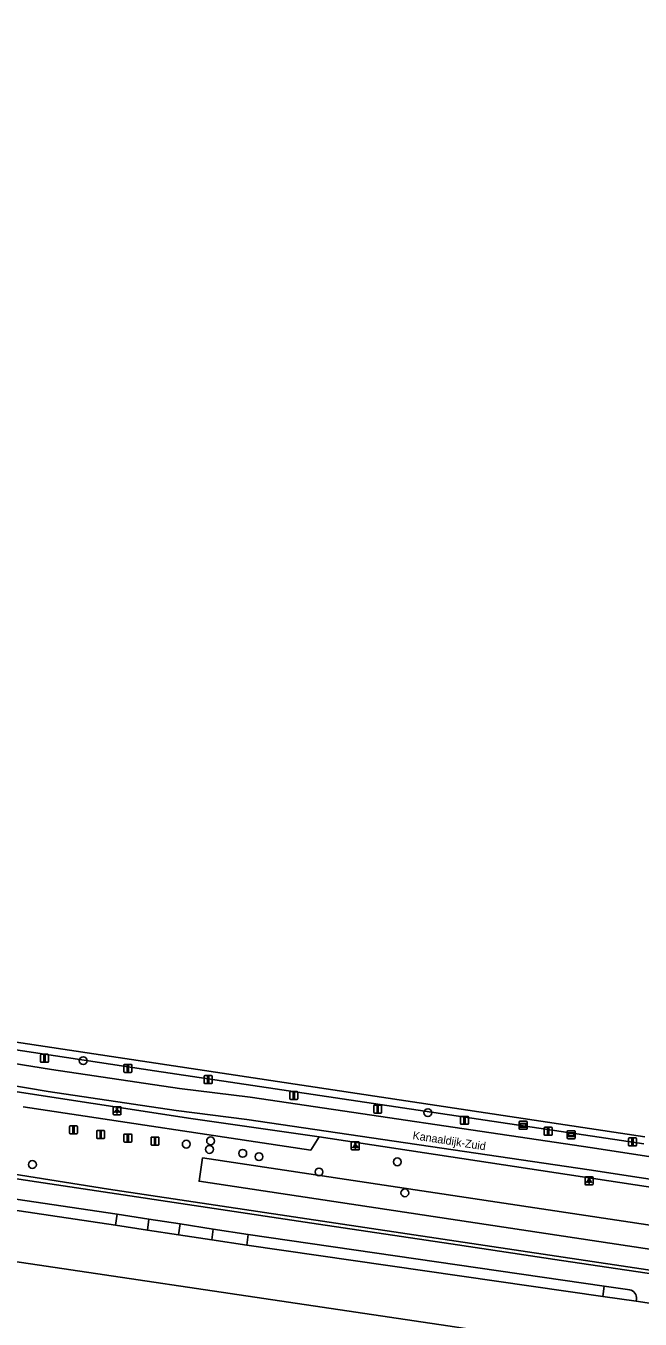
# Model space of a CAD drawing. Extents: x 163046 to 165074, y 382019 to 382874.
# Drawn here: x 164207.3 to 164284.1, y 382656.8 to 382818.4 of the extents above; entities that cross this region are included whole.
import ezdxf

# ---------------------------------------------------------------- set-up
doc = ezdxf.new("R2010")
doc.units = 0
for name, color, linetype in [('IMGEO_Afsluitpaal', 7, 'Continuous'), ('IMGEO_Boom', 7, 'Continuous'), ('IMGEO_Fietspad_gesloten', 7, 'Continuous'), ('IMGEO_Fietspad_open', 7, 'Continuous'), ('IMGEO_Groenvoorziening', 7, 'Continuous'), ('IMGEO_Hek', 7, 'Continuous'), ('IMGEO_Lichtpunt', 7, 'Continuous'), ('IMGEO_Openbare_ruimte_label', 7, 'Continuous'), ('IMGEO_Rijbaan_lokaal_gesloten', 7, 'Continuous'), ('IMGEO_Rijbaan_lokaal_halfverhard', 7, 'Continuous'), ('IMGEO_Verklikker', 7, 'Continuous'), ('IMGEO_Voetpad_open', 7, 'Continuous'), ('IMGEO_Waterloop', 7, 'Continuous')]:
    doc.layers.add(name, color=color, linetype=linetype)

msp = doc.modelspace()

# ---------------------------------------------------------------- linework, layer by layer
at = {"layer": 'IMGEO_Afsluitpaal'}
for p, q in [((164209.15, 382689.01), (164209.15, 382689.81)), ((164209.15, 382689.81), (164209.15, 382689.01)), ((164209.25, 382689.91), (164210.04, 382689.91)), ((164210.04, 382689.91), (164209.25, 382689.91)), ((164210.04, 382688.91), (164209.25, 382688.91)), ((164209.25, 382688.91), (164210.04, 382688.91)), ((164210.14, 382689.81), (164210.14, 382689.01)), ((164210.14, 382689.01), (164210.14, 382689.81)), ((164219.56, 382687.75), (164219.56, 382688.55)), ((164219.56, 382688.55), (164219.56, 382687.75)), ((164219.66, 382688.65), (164220.45, 382688.65)), ((164220.45, 382688.65), (164219.66, 382688.65)), ((164220.55, 382688.55), (164220.55, 382687.75)), ((164220.55, 382687.75), (164220.55, 382688.55)), ((164220.45, 382687.65), (164219.66, 382687.65)), ((164219.66, 382687.65), (164220.45, 382687.65)), ((164229.6, 382686.35), (164229.6, 382687.15)), ((164229.6, 382687.15), (164229.6, 382686.35)), ((164229.7, 382687.25), (164230.49, 382687.25)), ((164230.49, 382687.25), (164229.7, 382687.25)), ((164230.59, 382687.15), (164230.59, 382686.35)), ((164230.59, 382686.35), (164230.59, 382687.15)), ((164230.49, 382686.25), (164229.7, 382686.25)), ((164229.7, 382686.25), (164230.49, 382686.25)), ((164240.31, 382684.36), (164240.31, 382685.16)), ((164240.31, 382685.16), (164240.31, 382684.36)), ((164240.41, 382685.26), (164241.2, 382685.26)), ((164241.2, 382685.26), (164240.41, 382685.26)), ((164241.3, 382685.16), (164241.3, 382684.36)), ((164241.3, 382684.36), (164241.3, 382685.16)), ((164241.2, 382684.26), (164240.41, 382684.26)), ((164240.41, 382684.26), (164241.2, 382684.26)), ((164250.9, 382683.56), (164251.68, 382683.56)), ((164251.68, 382683.56), (164250.9, 382683.56)), ((164250.8, 382682.66), (164250.8, 382683.46)), ((164250.8, 382683.46), (164250.8, 382682.66)), ((164251.68, 382682.56), (164250.9, 382682.56)), ((164250.9, 382682.56), (164251.68, 382682.56)), ((164251.78, 382683.46), (164251.78, 382682.66)), ((164251.78, 382682.66), (164251.78, 382683.46)), ((164261.65, 382681.26), (164261.65, 382682.05)), ((164261.65, 382682.05), (164261.65, 382681.26)), ((164261.75, 382682.15), (164262.54, 382682.15)), ((164262.54, 382682.15), (164261.75, 382682.15)), ((164262.64, 382682.05), (164262.64, 382681.26)), ((164262.64, 382681.26), (164262.64, 382682.05)), ((164212.77, 382680.07), (164212.77, 382680.87)), ((164212.77, 382680.87), (164212.77, 382680.07)), ((164212.87, 382680.97), (164213.66, 382680.97)), ((164213.66, 382680.97), (164212.87, 382680.97)), ((164213.76, 382680.87), (164213.76, 382680.07)), ((164213.76, 382680.07), (164213.76, 382680.87)), ((164216.26, 382680.38), (164217.05, 382680.38)), ((164217.05, 382680.38), (164216.26, 382680.38)), ((164262.54, 382681.16), (164261.75, 382681.16)), ((164261.75, 382681.16), (164262.54, 382681.16)), ((164272.1, 382679.89), (164272.1, 382680.69)), ((164272.1, 382680.69), (164272.1, 382679.89)), ((164272.2, 382680.79), (164272.99, 382680.79)), ((164272.99, 382680.79), (164272.2, 382680.79)), ((164273.09, 382680.69), (164273.09, 382679.89)), ((164273.09, 382679.89), (164273.09, 382680.69)), ((164213.66, 382679.97), (164212.87, 382679.97)), ((164212.87, 382679.97), (164213.66, 382679.97)), ((164216.16, 382679.48), (164216.16, 382680.28)), ((164216.16, 382680.28), (164216.16, 382679.48)), ((164217.05, 382679.38), (164216.26, 382679.38)), ((164216.26, 382679.38), (164217.05, 382679.38)), ((164217.15, 382680.28), (164217.15, 382679.48)), ((164217.15, 382679.48), (164217.15, 382680.28)), ((164219.56, 382679.04), (164219.56, 382679.84)), ((164219.56, 382679.84), (164219.56, 382679.04)), ((164219.66, 382679.94), (164220.45, 382679.94)), ((164220.45, 382679.94), (164219.66, 382679.94)), ((164220.45, 382678.94), (164219.66, 382678.94)), ((164219.66, 382678.94), (164220.45, 382678.94)), ((164220.55, 382679.84), (164220.55, 382679.04)), ((164220.55, 382679.04), (164220.55, 382679.84)), ((164222.96, 382678.67), (164222.96, 382679.47)), ((164222.96, 382679.47), (164222.96, 382678.67)), ((164223.06, 382679.57), (164223.85, 382679.57)), ((164223.85, 382679.57), (164223.06, 382679.57)), ((164223.95, 382679.47), (164223.95, 382678.67)), ((164223.95, 382678.67), (164223.95, 382679.47)), ((164272.99, 382679.79), (164272.2, 382679.79)), ((164272.2, 382679.79), (164272.99, 382679.79)), ((164282.66, 382678.56), (164282.66, 382679.36)), ((164282.66, 382679.36), (164282.66, 382678.56)), ((164282.76, 382679.46), (164283.55, 382679.46)), ((164283.55, 382679.46), (164282.76, 382679.46)), ((164283.65, 382679.36), (164283.65, 382678.56)), ((164283.65, 382678.56), (164283.65, 382679.36)), ((164223.85, 382678.57), (164223.06, 382678.57)), ((164223.06, 382678.57), (164223.85, 382678.57)), ((164283.55, 382678.46), (164282.76, 382678.46)), ((164282.76, 382678.46), (164283.55, 382678.46))]:
    msp.add_line(p, q, dxfattribs=at)
for points in [[(164209.57, 382689.78), (164209.72, 382689.78), (164209.72, 382689.03), (164209.57, 382689.03), (164209.57, 382689.78)], [(164219.98, 382688.53), (164220.13, 382688.53), (164220.13, 382687.78), (164219.98, 382687.78), (164219.98, 382688.53)], [(164230.02, 382687.12), (164230.17, 382687.12), (164230.17, 382686.38), (164230.02, 382686.38), (164230.02, 382687.12)], [(164240.73, 382685.13), (164240.88, 382685.13), (164240.88, 382684.38), (164240.73, 382684.38), (164240.73, 382685.13)], [(164251.21, 382683.43), (164251.37, 382683.43), (164251.37, 382682.68), (164251.21, 382682.68), (164251.21, 382683.43)], [(164262.07, 382682.03), (164262.22, 382682.03), (164262.22, 382681.28), (164262.07, 382681.28), (164262.07, 382682.03)], [(164213.19, 382680.85), (164213.34, 382680.85), (164213.34, 382680.1), (164213.19, 382680.1), (164213.19, 382680.85)], [(164272.52, 382680.66), (164272.67, 382680.66), (164272.67, 382679.91), (164272.52, 382679.91), (164272.52, 382680.66)], [(164216.58, 382680.26), (164216.73, 382680.26), (164216.73, 382679.51), (164216.58, 382679.51), (164216.58, 382680.26)], [(164219.98, 382679.82), (164220.13, 382679.82), (164220.13, 382679.07), (164219.98, 382679.07), (164219.98, 382679.82)], [(164223.38, 382679.45), (164223.53, 382679.45), (164223.53, 382678.7), (164223.38, 382678.7), (164223.38, 382679.45)], [(164283.08, 382679.34), (164283.23, 382679.34), (164283.23, 382678.59), (164283.08, 382678.59), (164283.08, 382679.34)]]:
    msp.add_lwpolyline(points, dxfattribs=at)
for centre, start, end in [((164209.25, 382689.81), 90, 180), ((164209.25, 382689.81), 90, 180), ((164209.25, 382689.01), 180, 270), ((164209.25, 382689.01), 180, 270), ((164210.04, 382689.81), 0, 90), ((164210.04, 382689.81), 360, 90), ((164210.04, 382689.01), 270, 0), ((164210.04, 382689.01), 270, 0), ((164219.66, 382688.55), 90, 180), ((164219.66, 382688.55), 90, 180), ((164220.45, 382688.55), 0, 90), ((164220.45, 382688.55), 360, 90), ((164219.66, 382687.75), 180, 270), ((164219.66, 382687.75), 180, 270), ((164220.45, 382687.75), 270, 0), ((164220.45, 382687.75), 270, 0), ((164229.7, 382687.15), 90, 180), ((164229.7, 382687.15), 90, 180), ((164230.49, 382687.15), 0, 90), ((164230.49, 382687.15), 360, 90), ((164229.7, 382686.35), 180, 270), ((164229.7, 382686.35), 180, 270), ((164230.49, 382686.35), 270, 0), ((164230.49, 382686.35), 270, 0), ((164240.41, 382685.16), 90, 180), ((164240.41, 382685.16), 90, 180), ((164241.2, 382685.16), 0, 90), ((164241.2, 382685.16), 360, 90), ((164240.41, 382684.36), 180, 270), ((164240.41, 382684.36), 180, 270), ((164241.2, 382684.36), 270, 0), ((164241.2, 382684.36), 270, 0), ((164250.9, 382683.46), 90, 180), ((164250.9, 382683.46), 90, 180), ((164251.68, 382683.46), 0, 90), ((164251.68, 382683.46), 360, 90), ((164250.9, 382682.66), 180, 270), ((164250.9, 382682.66), 180, 270), ((164251.68, 382682.66), 270, 0), ((164251.68, 382682.66), 270, 0), ((164261.75, 382682.05), 90, 180), ((164261.75, 382682.05), 90, 180), ((164262.54, 382682.05), 0, 90), ((164262.54, 382682.05), 360, 90), ((164212.87, 382680.87), 90, 180), ((164212.87, 382680.87), 90, 180), ((164213.66, 382680.87), 0, 90), ((164213.66, 382680.87), 360, 90), ((164216.26, 382680.28), 90, 180), ((164216.26, 382680.28), 90, 180), ((164217.05, 382680.28), 0, 90), ((164217.05, 382680.28), 360, 90), ((164261.75, 382681.26), 180, 270), ((164261.75, 382681.26), 180, 270), ((164262.54, 382681.26), 270, 0), ((164262.54, 382681.26), 270, 0), ((164272.2, 382680.69), 90, 180), ((164272.2, 382680.69), 90, 180), ((164272.99, 382680.69), 0, 90), ((164272.99, 382680.69), 360, 90), ((164212.87, 382680.07), 180, 270), ((164212.87, 382680.07), 180, 270), ((164213.66, 382680.07), 270, 0), ((164213.66, 382680.07), 270, 0), ((164216.26, 382679.48), 180, 270), ((164216.26, 382679.48), 180, 270), ((164217.05, 382679.48), 270, 0), ((164217.05, 382679.48), 270, 0), ((164219.66, 382679.84), 90, 180), ((164219.66, 382679.84), 90, 180), ((164219.66, 382679.04), 180, 270), ((164219.66, 382679.04), 180, 270), ((164220.45, 382679.84), 0, 90), ((164220.45, 382679.84), 360, 90), ((164220.45, 382679.04), 270, 0), ((164220.45, 382679.04), 270, 0), ((164223.06, 382679.47), 90, 180), ((164223.06, 382679.47), 90, 180), ((164223.06, 382678.67), 180, 270), ((164223.06, 382678.67), 180, 270), ((164223.85, 382679.47), 0, 90), ((164223.85, 382679.47), 360, 90), ((164223.85, 382678.67), 270, 0), ((164223.85, 382678.67), 270, 0), ((164272.2, 382679.89), 180, 270), ((164272.2, 382679.89), 180, 270), ((164272.99, 382679.89), 270, 0), ((164272.99, 382679.89), 270, 0), ((164282.76, 382679.36), 90, 180), ((164282.76, 382679.36), 90, 180), ((164283.55, 382679.36), 0, 90), ((164283.55, 382679.36), 360, 90), ((164282.76, 382678.56), 180, 270), ((164282.76, 382678.56), 180, 270), ((164283.55, 382678.56), 270, 0), ((164283.55, 382678.56), 270, 0)]:
    msp.add_arc(centre, 0.1, start, end, dxfattribs=at)
at = {"layer": 'IMGEO_Boom'}
for centre in [(164214.48, 382689.11), (164257.56, 382682.62), (164227.36, 382678.68), (164230.4, 382679.09), (164230.26, 382678.02), (164234.42, 382677.53), (164236.45, 382677.11), (164208.13, 382676.13), (164243.95, 382675.2), (164253.74, 382676.47), (164254.69, 382672.59)]:
    msp.add_circle(centre, 0.489, dxfattribs=at)
at = {"layer": 'IMGEO_Fietspad_gesloten'}
for points in [[(164290.62, 382661.73), (164274.25, 382664.12), (164260.42, 382666.24), (164243.89, 382668.69), (164144.23, 382683.65), (164123, 382686.71), (164101.01, 382689.99), (164076.37, 382693.78), (164055.27, 382696.95), (164027.35, 382701.08), (164001.81, 382704.9), (163972.99, 382709.21), (163941.3, 382713.95), (163899.36, 382720.17), (163864.59, 382725.29), (163853.75, 382726.93), (163828.34, 382730.66), (163782.57, 382737.3), (163742.98, 382743.16), (163672.74, 382753.5), (163608.81, 382762.9), (163587.4, 382766.11), (163537.53, 382773.31), (163534.17, 382773.83)], [(163935.71, 382729.35), (163983.8, 382722.23), (164052.71, 382712.03), (164052.69, 382711.93), (164086.54, 382706.99), (164187.43, 382691.72), (164210.53, 382688.01), (164226.5, 382685.65), (164235.35, 382684.54), (164278.14, 382678.22), (164284.35, 382677.28), (164396.3, 382660.19), (164454.95, 382651.33), (164514.06, 382642.55), (164543.13, 382638.08), (164564.45, 382634.88), (164577.4, 382632.94), (164578.83, 382632.68), (164590.1, 382630.98)], [(164085.34, 382689.67), (164218.72, 382669.95)], [(164218.72, 382669.95), (164222.69, 382669.32)], [(164222.69, 382669.32), (164226.59, 382668.71)], [(164226.59, 382668.71), (164230.72, 382668.06)], [(164230.72, 382668.06), (164235.1, 382667.37)], [(164235.1, 382667.37), (164279.62, 382660.93)], [(164279.62, 382660.93), (164282.79, 382660.47)], [(164283.63, 382659.34), (164283.59, 382659.04)]]:
    msp.add_lwpolyline(points, dxfattribs=at)
msp.add_arc((164282.64, 382659.48), 0.999, 351.5194, 81.6371, dxfattribs=at)
at = {"layer": 'IMGEO_Fietspad_open'}
for points in [[(164226.4, 382667.35), (164226.59, 382668.71)], [(164230.72, 382668.06), (164230.55, 382666.71)]]:
    msp.add_lwpolyline(points, dxfattribs=at)
at = {"layer": 'IMGEO_Groenvoorziening'}
for points in [[(163359.37, 382797.83), (163374.85, 382798.03), (163401.89, 382794.15), (163410.94, 382792.85), (163500, 382779.47), (163535.41, 382774.6), (163550.62, 382772.33), (163693.06, 382751.36), (163828.8, 382731.36), (163846.1, 382728.88), (163873.33, 382724.84), (163916.5, 382718.52), (163943.51, 382714.37), (163981.6, 382708.67), (164080.42, 382694.02), (164103.91, 382690.52), (164197.42, 382676.27), (164217.65, 382673.07), (164282.56, 382663.33), (164518.36, 382627.93)], [(164284.55, 382678.7), (164223.39, 382687.83), (164004.16, 382721.06), (164000, 382721.52), (163996.62, 382722), (163984.14, 382724.05), (163984.26, 382724.67)], [(164243.96, 382679.59), (164242.92, 382677.94), (164206.98, 382683.34)]]:
    msp.add_lwpolyline(points, dxfattribs=at)
at = {"layer": 'IMGEO_Hek'}
for points in [[(164282.56, 382663.33), (164217.65, 382673.07), (164197.42, 382676.27), (164103.91, 382690.52), (164080.42, 382694.02), (163981.6, 382708.67)], [(164518.36, 382627.93), (164282.56, 382663.33)]]:
    msp.add_lwpolyline(points, dxfattribs=at)
at = {"layer": 'IMGEO_Lichtpunt'}
for p, q in [((164218.21, 382683.26), (164218.21, 382682.46)), ((164218.21, 382683.26), (164218.21, 382682.46)), ((164219.11, 382683.36), (164218.3, 382683.36)), ((164219.11, 382683.36), (164218.3, 382683.36)), ((164218.3, 382682.36), (164219.11, 382682.36)), ((164218.3, 382682.36), (164219.11, 382682.36)), ((164219.2, 382682.46), (164219.2, 382683.26)), ((164219.2, 382682.46), (164219.2, 382683.26)), ((164247.99, 382678.86), (164247.99, 382678.05)), ((164247.99, 382678.86), (164247.99, 382678.05)), ((164248.89, 382678.95), (164248.09, 382678.95)), ((164248.89, 382678.95), (164248.09, 382678.95)), ((164248.99, 382678.05), (164248.99, 382678.86)), ((164248.99, 382678.05), (164248.99, 382678.86)), ((164248.09, 382677.96), (164248.89, 382677.96)), ((164248.09, 382677.96), (164248.89, 382677.96)), ((164277.22, 382674.49), (164277.22, 382673.69)), ((164277.22, 382674.49), (164277.22, 382673.69)), ((164278.12, 382674.59), (164277.31, 382674.59)), ((164278.12, 382674.59), (164277.31, 382674.59)), ((164278.21, 382673.69), (164278.21, 382674.49)), ((164278.21, 382673.69), (164278.21, 382674.49)), ((164277.31, 382673.59), (164278.12, 382673.59)), ((164277.31, 382673.59), (164278.12, 382673.59))]:
    msp.add_line(p, q, dxfattribs=at)
for points in [[(164218.58, 382682.93), (164218.62, 382682.9), (164218.43, 382682.64), (164218.39, 382682.67), (164218.58, 382682.93)], [(164218.68, 382682.88), (164218.73, 382682.88), (164218.73, 382682.56), (164218.68, 382682.56), (164218.68, 382682.88)], [(164218.79, 382682.9), (164218.83, 382682.93), (164219.02, 382682.66), (164218.98, 382682.64), (164218.79, 382682.9)], [(164248.37, 382678.52), (164248.4, 382678.49), (164248.22, 382678.23), (164248.18, 382678.26), (164248.37, 382678.52)], [(164248.47, 382678.47), (164248.52, 382678.47), (164248.52, 382678.15), (164248.47, 382678.15), (164248.47, 382678.47)], [(164248.58, 382678.49), (164248.62, 382678.52), (164248.8, 382678.26), (164248.76, 382678.23), (164248.58, 382678.49)], [(164277.59, 382674.16), (164277.63, 382674.13), (164277.44, 382673.87), (164277.4, 382673.89), (164277.59, 382674.16)], [(164277.69, 382674.11), (164277.74, 382674.11), (164277.74, 382673.79), (164277.69, 382673.79), (164277.69, 382674.11)], [(164277.8, 382674.13), (164277.84, 382674.16), (164278.03, 382673.89), (164277.99, 382673.87), (164277.8, 382674.13)]]:
    msp.add_lwpolyline(points, dxfattribs=at)
for centre in [(164218.71, 382683.06), (164248.49, 382678.66), (164277.72, 382674.29)]:
    msp.add_circle(centre, 0.0994, dxfattribs=at)
for centre, start, end in [((164218.3, 382683.26), 90, 180), ((164218.3, 382683.26), 90, 180), ((164218.3, 382682.46), 180, 270), ((164218.3, 382682.46), 180, 270), ((164219.11, 382683.26), 0, 90), ((164219.11, 382683.26), 0, 90), ((164219.11, 382682.46), 270, 0), ((164219.11, 382682.46), 270, 360), ((164248.09, 382678.86), 90, 180), ((164248.09, 382678.86), 90, 180), ((164248.89, 382678.86), 0, 90), ((164248.89, 382678.86), 0, 90), ((164248.09, 382678.05), 180, 270), ((164248.09, 382678.05), 180, 270), ((164248.89, 382678.05), 270, 0), ((164248.89, 382678.05), 270, 360), ((164277.31, 382674.49), 90, 180), ((164277.31, 382674.49), 90, 180), ((164278.12, 382674.49), 0, 90), ((164278.12, 382674.49), 0, 90), ((164277.31, 382673.69), 180, 270), ((164277.31, 382673.69), 180, 270), ((164278.12, 382673.69), 270, 0), ((164278.12, 382673.69), 270, 360)]:
    msp.add_arc(centre, 0.0946, start, end, dxfattribs=at)
at = {"layer": 'IMGEO_Rijbaan_lokaal_gesloten'}
for points in [[(164218.52, 382668.55), (164085.14, 382688.39)], [(164136.35, 382674.36), (164189.87, 382666.4), (164260.05, 382655.98), (164266.67, 382654.99)], [(164222.5, 382667.94), (164218.52, 382668.55)], [(164226.4, 382667.35), (164222.5, 382667.94)], [(164230.55, 382666.71), (164226.4, 382667.35)], [(164234.93, 382666.04), (164230.55, 382666.71)], [(164279.43, 382659.64), (164234.93, 382666.04)], [(164283.59, 382659.04), (164279.43, 382659.64)], [(164286.36, 382658.63), (164283.59, 382659.04)]]:
    msp.add_lwpolyline(points, dxfattribs=at)
at = {"layer": 'IMGEO_Rijbaan_lokaal_halfverhard'}
for points in [[(163322.47, 382818.43), (163367.47, 382810.55), (163392.06, 382806.33), (163416.38, 382802.09), (163437.86, 382798.77), (163477.86, 382792.74), (163535.08, 382784.39), (163586.49, 382776.8), (163665.19, 382765.27), (163724.04, 382756.55), (163797.09, 382745.94), (163942.52, 382724.63), (163982.95, 382718.82), (164038.68, 382710.5), (164106.21, 382700.45), (164167.93, 382691.09), (164227.93, 382681.9), (164243.96, 382679.59)], [(163935.2, 382726.45), (163983.27, 382719.37), (164086.12, 382704.22), (164199.47, 382687.05), (164210.1, 382685.24), (164226.11, 382682.88), (164234.94, 382681.77), (164277.72, 382675.46), (164283.96, 382674.5), (164395.88, 382657.42), (164454.54, 382648.56), (164513.64, 382639.78), (164542.71, 382635.32), (164564.09, 382632.1), (164578.55, 382629.91), (164583.76, 382629.04)], [(164563.98, 382631.34), (164546.63, 382633.89), (164490.17, 382642.3), (164454.45, 382647.37), (164396.2, 382656.23), (164325.74, 382667.17), (164243.96, 382679.59)]]:
    msp.add_lwpolyline(points, dxfattribs=at)
at = {"layer": 'IMGEO_Verklikker'}
for p, q in [((164268.98, 382680.64), (164268.98, 382681.44)), ((164268.98, 382681.44), (164268.98, 382680.64)), ((164269.08, 382681.54), (164269.87, 382681.54)), ((164269.87, 382681.54), (164269.08, 382681.54)), ((164269.87, 382680.54), (164269.08, 382680.54)), ((164269.08, 382680.54), (164269.87, 382680.54)), ((164269.97, 382681.44), (164269.97, 382680.64)), ((164269.97, 382680.64), (164269.97, 382681.44)), ((164275.07, 382680.36), (164275.86, 382680.36)), ((164275.86, 382680.36), (164275.07, 382680.36)), ((164274.97, 382679.46), (164274.97, 382680.26)), ((164274.97, 382680.26), (164274.97, 382679.46)), ((164275.86, 382679.36), (164275.07, 382679.36)), ((164275.07, 382679.36), (164275.86, 382679.36)), ((164275.96, 382680.26), (164275.96, 382679.46)), ((164275.96, 382679.46), (164275.96, 382680.26))]:
    msp.add_line(p, q, dxfattribs=at)
for points in [[(164269.09, 382681.27), (164269.87, 382681.27), (164269.87, 382680.81), (164269.09, 382680.81), (164269.09, 382681.27)], [(164269.15, 382681.21), (164269.15, 382680.87), (164269.81, 382680.87), (164269.81, 382681.21), (164269.15, 382681.21)], [(164275.07, 382680.1), (164275.86, 382680.1), (164275.86, 382679.63), (164275.07, 382679.63), (164275.07, 382680.1)], [(164275.14, 382680.03), (164275.14, 382679.7), (164275.8, 382679.7), (164275.8, 382680.03), (164275.14, 382680.03)]]:
    msp.add_lwpolyline(points, dxfattribs=at)
for centre, start, end in [((164269.08, 382681.44), 90, 180), ((164269.08, 382681.44), 90, 180), ((164269.08, 382680.64), 180, 270), ((164269.08, 382680.64), 180, 270), ((164269.87, 382681.44), 0, 90), ((164269.87, 382681.44), 360, 90), ((164269.87, 382680.64), 270, 0), ((164269.87, 382680.64), 270, 0), ((164275.07, 382680.26), 90, 180), ((164275.07, 382680.26), 90, 180), ((164275.86, 382680.26), 0, 90), ((164275.86, 382680.26), 360, 90), ((164275.07, 382679.46), 180, 270), ((164275.07, 382679.46), 180, 270), ((164275.86, 382679.46), 270, 0), ((164275.86, 382679.46), 270, 0)]:
    msp.add_arc(centre, 0.1, start, end, dxfattribs=at)
at = {"layer": 'IMGEO_Voetpad_open'}
for points in [[(164218.52, 382668.55), (164218.72, 382669.95)], [(164222.69, 382669.32), (164222.5, 382667.94)], [(164234.93, 382666.04), (164235.1, 382667.37)], [(164279.62, 382660.93), (164279.43, 382659.64)]]:
    msp.add_lwpolyline(points, dxfattribs=at)
at = {"layer": 'IMGEO_Waterloop'}
for points in [[(163984.26, 382724.67), (164000, 382722.46), (164284.68, 382679.59)], [(164229.4, 382676.95), (164337.68, 382660.69), (164416.83, 382649.81), (164431.81, 382647.48), (164450.46, 382644.94), (164486.15, 382640.16), (164500, 382638.01), (164542.07, 382631.47), (164541.63, 382628.3), (164500, 382634.6), (164485.67, 382636.85), (164404.8, 382648.54), (164314.83, 382661.08), (164228.97, 382674.04), (164229.4, 382676.95)]]:
    msp.add_lwpolyline(points, dxfattribs=at)

# ---------------------------------------------------------------- texts
at = {"layer": 'IMGEO_Openbare_ruimte_label'}
msp.add_text('Kanaaldijk-Zuid', height=1, rotation=351.2538, dxfattribs=at).set_placement((164255.61, 382679.31))

doc.saveas('drawing.dxf')
